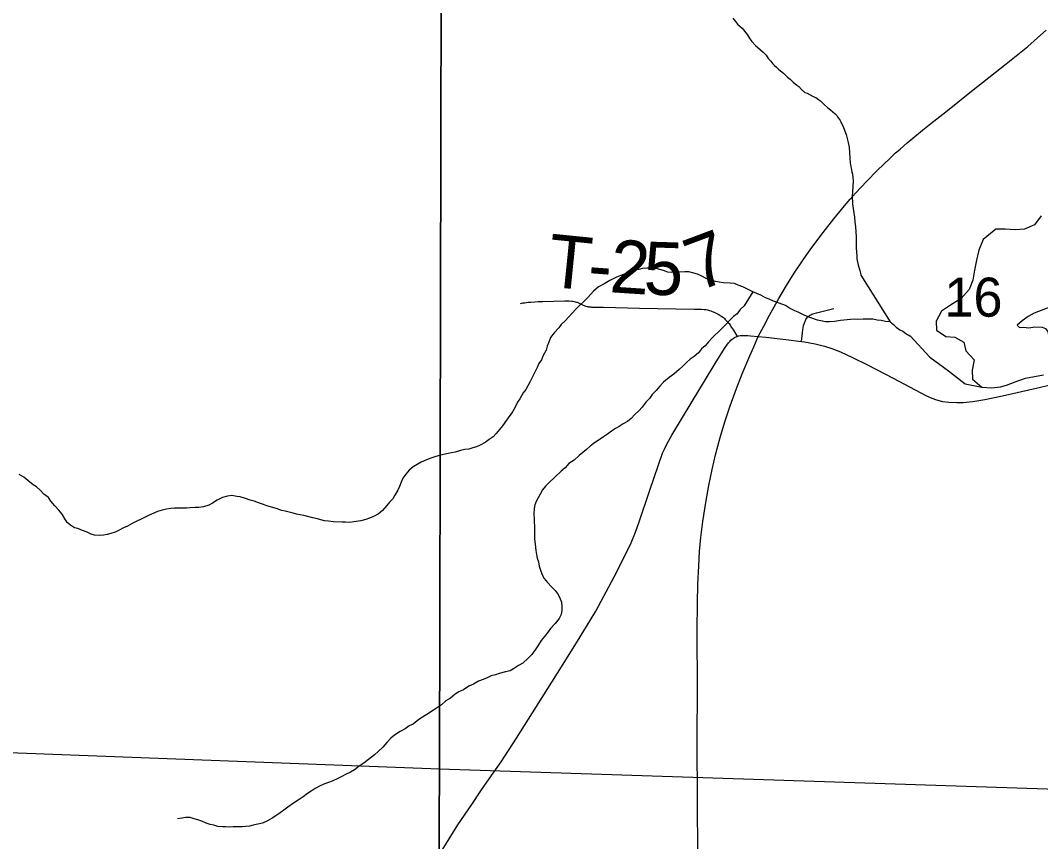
# Model space of a CAD drawing. Extents: x 0 to 34, y 0 to 22.
# Drawn here: x 24.814 to 25.361, y 13.769 to 14.209 of the extents above; entities that cross this region are included whole.
import ezdxf

# ---------------------------------------------------------------- set-up
doc = ezdxf.new("R2010")
doc.units = 0
for name, color, linetype in [('GM_X_County_Road', 7, 'Continuous'), ('GM_X_Major_River', 7, 'Continuous'), ('GM_X_Minor_River', 7, 'Continuous'), ('GM_X_Section', 7, 'Continuous'), ('GM_X_Section_Text', 7, 'Continuous'), ('GM_X_Township_Road', 7, 'Continuous'), ('GM_X_Township_Road_Text', 7, 'Continuous'), ('GM_X_Unincorporated', 7, 'Continuous'), ('GM_X_US_Route', 7, 'Continuous')]:
    doc.layers.add(name, color=color, linetype=linetype)

msp = doc.modelspace()

# ---------------------------------------------------------------- linework, layer by layer
at = {"layer": 'GM_X_County_Road'}
for points in [[(25.03643, 13.7579), (25.04495, 13.77146), (25.04871, 13.77745), (25.05619, 13.78851), (25.06101, 13.79576), (25.06545, 13.80214), (25.07183, 13.81128), (25.08004, 13.82406), (25.08654, 13.83428), (25.10424, 13.86239), (25.11284, 13.87606), (25.1197, 13.88715), (25.1227, 13.8922), (25.13253, 13.91053), (25.13648, 13.91827), (25.14155, 13.92891), (25.14397, 13.9346), (25.14598, 13.94012), (25.15149, 13.95661), (25.15621, 13.97075), (25.15846, 13.9769), (25.15945, 13.97919), (25.16068, 13.98171), (25.1634, 13.98663), (25.17439, 14.00466), (25.18105, 14.01551), (25.18729, 14.02589), (25.19212, 14.0336), (25.19388, 14.03618), (25.19467, 14.03707), (25.19518, 14.03756), (25.19585, 14.03814), (25.19631, 14.0385), (25.19699, 14.03895), (25.19742, 14.03919), (25.1985, 14.03963)], [(25.1985, 14.03963), (25.19941, 14.03989), (25.20017, 14.04005), (25.20098, 14.04014), (25.20169, 14.04018), (25.20254, 14.04018), (25.20329, 14.04015), (25.20417, 14.04011), (25.20572, 14.03998), (25.20974, 14.03956)], [(25.20974, 14.03956), (25.21393, 14.03913), (25.22464, 14.03789), (25.23294, 14.03686)], [(25.23294, 14.03686), (25.23465, 14.03661), (25.2403, 14.03564), (25.24536, 14.03446), (25.24921, 14.03315), (25.25388, 14.03136), (25.26039, 14.02836), (25.2684, 14.02427), (25.27777, 14.01945), (25.28221, 14.01722), (25.29401, 14.01095), (25.30004, 14.00778), (25.30285, 14.00652), (25.30544, 14.00559), (25.3087, 14.00476), (25.31203, 14.00425), (25.31632, 14.00407), (25.3197, 14.00418), (25.32492, 14.00475), (25.33134, 14.00578), (25.34075, 14.00779), (25.35892, 14.01191), (25.3665, 14.01358)]]:
    msp.add_lwpolyline(points, dxfattribs=at)
at = {"layer": 'GM_X_Major_River'}
msp.add_lwpolyline([(25.37171, 14.05751), (25.35771, 14.05216), (25.35463, 14.05034), (25.35134, 14.04796), (25.34862, 14.04556), (25.34992, 14.04439), (25.35201, 14.04452), (25.35486, 14.04426), (25.3581, 14.04475), (25.36208, 14.04465), (25.36396, 14.04384), (25.36524, 14.04191), (25.36557, 14.03963)], dxfattribs=at)
at = {"layer": 'GM_X_Minor_River'}
for points in [[(25.19614, 14.21036), (25.19759, 14.2086), (25.19868, 14.20724), (25.19996, 14.20605), (25.20125, 14.20506), (25.20377, 14.20155), (25.2052, 14.19922), (25.20629, 14.19786), (25.20829, 14.1957), (25.20958, 14.19471), (25.21251, 14.19214), (25.21397, 14.19057), (25.2145, 14.1896), (25.21522, 14.18862), (25.2165, 14.18725), (25.2174, 14.18608), (25.21849, 14.1849), (25.2196, 14.1841), (25.22069, 14.18293), (25.2218, 14.18213), (25.22327, 14.18094), (25.22418, 14.17996), (25.22546, 14.17877), (25.22693, 14.17758), (25.22858, 14.17601), (25.23042, 14.17443), (25.23152, 14.17363), (25.23298, 14.17206), (25.23481, 14.17047), (25.23612, 14.17005), (25.23761, 14.16924), (25.23928, 14.16842), (25.24077, 14.1678), (25.24206, 14.16681), (25.24317, 14.16601), (25.24427, 14.16502), (25.24518, 14.16404), (25.2472, 14.16226), (25.24849, 14.16127), (25.24977, 14.16008), (25.25106, 14.15909), (25.25197, 14.15811), (25.25268, 14.15694), (25.25359, 14.15577), (25.25412, 14.15481), (25.25552, 14.15172), (25.25689, 14.14787), (25.25757, 14.14576), (25.25806, 14.14365), (25.25854, 14.14117), (25.25881, 14.13831), (25.25889, 14.13527), (25.25917, 14.13279), (25.25948, 14.13069), (25.2598, 14.12916), (25.25994, 14.12783), (25.26028, 14.12668)], [(25.26028, 14.12668), (25.26059, 14.12496), (25.26071, 14.12305), (25.2603, 14.11718), (25.26023, 14.1151), (25.26044, 14.11053), (25.26103, 14.10595), (25.26151, 14.10366), (25.2616, 14.10099), (25.26188, 14.09833), (25.26216, 14.09566), (25.26225, 14.093), (25.26233, 14.08995), (25.26241, 14.0871), (25.26252, 14.08482), (25.26264, 14.08292), (25.26276, 14.0812), (25.26339, 14.07776), (25.26423, 14.07489), (25.26456, 14.07355), (25.2649, 14.07239), (25.28064, 14.04735), (25.28229, 14.04597), (25.28376, 14.04459), (25.28579, 14.04319), (25.28727, 14.04238), (25.28893, 14.04118), (25.29116, 14.03996), (25.29126, 14.03991)], [(25.36149, 14.10427), (25.35795, 14.09943), (25.35257, 14.09709), (25.34763, 14.09684), (25.34232, 14.09716), (25.33719, 14.0971), (25.3304, 14.09158), (25.32817, 14.08594), (25.32689, 14.08047), (25.32581, 14.07518), (25.32491, 14.0697), (25.32289, 14.06481), (25.31859, 14.05998), (25.31299, 14.05633), (25.30816, 14.05322), (25.30518, 14.04779), (25.30544, 14.04304), (25.31048, 14.0395), (25.31522, 14.03919), (25.32009, 14.0366), (25.32112, 14.03182), (25.32555, 14.02697), (25.32446, 14.02149), (25.32472, 14.01674), (25.32975, 14.01243), (25.33486, 14.01193), (25.33982, 14.01256), (25.34288, 14.01343)], [(25.28064, 14.04735), (25.27803, 14.04763), (25.27577, 14.04809), (25.2735, 14.04836), (25.27123, 14.04882), (25.26876, 14.04891), (25.2661, 14.04881), (25.26325, 14.04873), (25.26116, 14.0488), (25.25925, 14.04868), (25.25391, 14.04811), (25.25066, 14.04766), (25.2478, 14.04738), (25.2459, 14.04745), (25.24345, 14.04791), (25.24157, 14.04836), (25.238, 14.04963), (25.23481, 14.05089), (25.23126, 14.05254), (25.22939, 14.05336), (25.22659, 14.05479), (25.22436, 14.05621), (25.22099, 14.05747), (25.21798, 14.05853), (25.21574, 14.05956), (25.21368, 14.06039), (25.21126, 14.06181), (25.20695, 14.06349), (25.2047, 14.06452), (25.20153, 14.06615), (25.1991, 14.06719), (25.19704, 14.06803), (25.19476, 14.06811), (25.19116, 14.06843), (25.18889, 14.0687), (25.18681, 14.06915), (25.18418, 14.06982), (25.18193, 14.07066), (25.1795, 14.07189), (25.17726, 14.07292), (25.17519, 14.07356), (25.17255, 14.07423), (25.17046, 14.0743), (25.16627, 14.07407), (25.16323, 14.07399), (25.16133, 14.07406), (25.15889, 14.07491), (25.15513, 14.07599), (25.15267, 14.07627), (25.15, 14.07618), (25.14772, 14.07607), (25.1458, 14.07557), (25.1435, 14.07508), (25.14061, 14.07404), (25.13753, 14.07282), (25.13368, 14.07144), (25.13019, 14.06966), (25.12747, 14.06805), (25.12418, 14.06626), (25.12143, 14.06389), (25.11846, 14.06057), (25.11629, 14.05837), (25.11393, 14.05617), (25.11215, 14.05433), (25.10998, 14.05212), (25.108, 14.04991), (25.10622, 14.04788), (25.10406, 14.04606), (25.10285, 14.0442), (25.10028, 14.04144), (25.0983, 14.03904), (25.09745, 14.0366), (25.09661, 14.03435), (25.09596, 14.03228), (25.09452, 14.02928), (25.09349, 14.02704), (25.09209, 14.025), (25.09125, 14.02294), (25.09024, 14.02107), (25.08901, 14.01864), (25.08736, 14.01509), (25.08513, 14.01117), (25.08373, 14.00932), (25.08191, 14.00615), (25.0807, 14.00429), (25.07946, 14.00167), (25.07804, 13.99906), (25.07484, 13.99461), (25.07264, 13.99165), (25.07105, 13.98961), (25.06926, 13.98758), (25.06768, 13.98574), (25.06553, 13.98429), (25.06338, 13.98266), (25.06067, 13.98123), (25.05874, 13.98035), (25.05663, 13.97986), (25.05451, 13.97917), (25.05241, 13.97887)], [(25.20695, 14.06349), (25.20231, 14.05604), (25.20014, 14.05403), (25.19854, 14.05181), (25.19659, 14.05035), (25.19462, 14.04833), (25.19303, 14.04649), (25.18988, 14.04356), (25.18515, 14.03878), (25.18318, 14.03676), (25.18138, 14.03454), (25.17942, 14.0329), (25.17783, 14.03086), (25.17548, 14.02886), (25.17334, 14.02741), (25.17137, 14.02558), (25.1694, 14.02356), (25.16744, 14.02192), (25.16449, 14.01936), (25.16196, 14.01755), (25.15901, 14.01499), (25.15704, 14.01297), (25.15505, 14.01057), (25.15288, 14.00836), (25.15148, 14.00632), (25.14951, 14.0043), (25.14751, 14.00171), (25.14573, 13.99968), (25.14356, 13.99767), (25.14159, 13.99564), (25.13963, 13.994), (25.13731, 13.99275), (25.13516, 13.99131), (25.13322, 13.99024), (25.13108, 13.98879), (25.12893, 13.98716), (25.12679, 13.98571), (25.12387, 13.98373), (25.12192, 13.98246), (25.11957, 13.98065), (25.11761, 13.979), (25.11565, 13.97736), (25.11369, 13.97572), (25.11113, 13.97315), (25.10821, 13.97135), (25.10623, 13.96914), (25.10408, 13.96732), (25.09739, 13.96109), (25.09561, 13.95925), (25.09402, 13.95722), (25.0928, 13.95498), (25.09177, 13.95292), (25.09076, 13.95106), (25.08993, 13.94918), (25.08967, 13.94729), (25.08938, 13.94445), (25.08966, 13.94159), (25.08984, 13.93625), (25.08974, 13.9334), (25.08984, 13.93074), (25.09012, 13.92806), (25.09057, 13.92481), (25.09087, 13.92252), (25.09118, 13.92061), (25.09187, 13.91868), (25.09236, 13.91638), (25.09304, 13.91426), (25.0939, 13.91176), (25.09497, 13.90963), (25.09679, 13.90747), (25.09881, 13.9055), (25.10082, 13.90333), (25.10246, 13.90118), (25.10351, 13.89886), (25.1042, 13.89694), (25.1045, 13.89464), (25.10443, 13.89274), (25.10416, 13.89047), (25.10294, 13.88823), (25.10095, 13.88564), (25.09838, 13.88288), (25.09717, 13.88102), (25.09518, 13.87862), (25.09339, 13.8764), (25.09198, 13.87417), (25.09017, 13.87138), (25.08837, 13.86897), (25.0864, 13.86695), (25.08345, 13.8642), (25.08112, 13.86296), (25.07859, 13.86115), (25.07665, 13.86007), (25.07416, 13.85959), (25.0709, 13.85876), (25.06878, 13.85807), (25.06648, 13.8574), (25.06435, 13.85633), (25.06223, 13.85545)], [(25.29126, 14.03991), (25.3018, 14.02847), (25.31185, 14.02107), (25.32083, 14.0142), (25.32975, 14.01243)], [(25.34288, 14.01343), (25.34767, 14.01521), (25.35323, 14.01716), (25.358, 14.01818), (25.36277, 14.01901)], [(25.05241, 13.97887), (25.05012, 13.97838), (25.04723, 13.97753), (25.04532, 13.97722), (25.0434, 13.97672), (25.04091, 13.97624), (25.03881, 13.97574), (25.03689, 13.97524), (25.03419, 13.9742), (25.03188, 13.97333), (25.02898, 13.9721), (25.02471, 13.96959), (25.02255, 13.96776), (25.02077, 13.96574), (25.01917, 13.96351), (25.01833, 13.96145), (25.0173, 13.95901), (25.01647, 13.95714), (25.01485, 13.95435), (25.01383, 13.95248), (25.01205, 13.95064), (25.01066, 13.94879), (25.00828, 13.94621), (25.00593, 13.9442), (25.00341, 13.94296), (25.00129, 13.94209), (24.99937, 13.9414), (24.99668, 13.94073), (24.99286, 13.94011), (24.99056, 13.93981), (24.98848, 13.93988), (24.98658, 13.93995), (24.98202, 13.94012), (24.97937, 13.9404), (24.9771, 13.94067), (24.97522, 13.94112), (24.97334, 13.94176), (24.97088, 13.94223), (24.96599, 13.94354), (24.96221, 13.94425), (24.96033, 13.9447), (24.956, 13.9458), (24.95411, 13.94625), (24.95186, 13.94709), (24.94998, 13.94754), (24.9481, 13.94818), (24.94621, 13.94863), (24.94434, 13.94945), (24.94171, 13.95031), (24.93946, 13.95115), (24.93721, 13.9518), (24.93477, 13.95265), (24.93195, 13.95351), (24.93005, 13.95377), (24.92741, 13.95425), (24.92512, 13.95395), (24.92243, 13.95309), (24.91952, 13.95168), (24.91699, 13.95005), (24.91506, 13.94898), (24.91217, 13.94813), (24.90969, 13.94784), (24.90779, 13.94772), (24.90493, 13.94763), (24.90303, 13.94751), (24.90093, 13.9474), (24.89866, 13.94748), (24.89675, 13.94736), (24.89466, 13.94724), (24.89236, 13.94694), (24.89006, 13.94645), (24.88756, 13.94559), (24.88563, 13.94471), (24.88274, 13.94348), (24.87945, 13.94189), (24.87616, 13.9403), (24.87403, 13.93923), (24.87151, 13.9378), (24.86938, 13.93693), (24.86706, 13.93568), (24.86493, 13.93461), (24.86262, 13.93393), (24.86051, 13.93325), (24.8586, 13.93294), (24.85631, 13.93283), (24.85384, 13.93292), (24.85197, 13.93355), (24.84991, 13.93458), (24.84728, 13.93544), (24.84485, 13.93647), (24.84296, 13.93692), (24.84092, 13.93833), (24.83907, 13.93972), (24.83764, 13.94206), (24.83638, 13.94419), (24.83456, 13.94635), (24.83255, 13.94871), (24.83037, 13.95126), (24.8291, 13.9532), (24.82651, 13.95501), (24.82487, 13.95697)], [(24.82487, 13.95697), (24.82266, 13.95895), (24.82079, 13.95997), (24.81803, 13.96235), (24.81581, 13.96414), (24.81339, 13.96556)], [(25.06223, 13.85545), (25.05972, 13.85459), (25.057, 13.85298), (25.0545, 13.85193), (25.05176, 13.84993), (25.04926, 13.84888), (25.04731, 13.84762), (25.04476, 13.84543), (25.04224, 13.844), (25.03988, 13.84199), (25.0356, 13.8391), (25.03209, 13.83675), (25.02879, 13.83478), (25.02684, 13.83333), (25.02468, 13.8315), (25.02256, 13.83063), (25.02041, 13.82899), (25.0177, 13.82757), (25.01477, 13.82558), (25.01281, 13.82394), (25.01064, 13.82174), (25.00846, 13.81915), (25.00591, 13.81696), (25.00394, 13.81513), (25.00081, 13.81258), (24.99827, 13.81058), (24.99574, 13.80895), (24.99319, 13.80695), (24.99106, 13.8057), (24.98835, 13.80446), (24.98641, 13.80339), (24.98428, 13.80233), (24.98119, 13.80092), (24.97927, 13.80022), (24.97676, 13.79936), (24.97445, 13.79831), (24.97212, 13.79706), (24.96998, 13.79561), (24.96803, 13.79435), (24.96569, 13.79253), (24.96296, 13.79073), (24.96043, 13.78911), (24.9575, 13.78693), (24.95536, 13.78548), (24.9534, 13.78403), (24.95106, 13.7824), (24.94912, 13.78114), (24.9466, 13.77971), (24.94389, 13.77848), (24.9414, 13.77781), (24.93891, 13.77732), (24.93699, 13.77682), (24.93489, 13.77671), (24.93298, 13.7764), (24.93032, 13.77649), (24.92823, 13.77638), (24.92632, 13.77625), (24.92424, 13.77652), (24.92234, 13.7764), (24.91988, 13.77668), (24.91781, 13.77732), (24.91574, 13.77777), (24.91367, 13.77842), (24.91142, 13.77945), (24.90917, 13.78029), (24.90729, 13.78074), (24.90503, 13.78139), (24.90275, 13.78147), (24.90065, 13.78117), (24.89835, 13.78068)]]:
    msp.add_lwpolyline(points, dxfattribs=at)
at = {"layer": 'GM_X_Section'}
for points in [[(24.53855, 14.33027), (25.03984, 14.31055), (25.03876, 13.80745), (24.53442, 13.82651)], [(25.03984, 14.31055), (25.53615, 14.29588), (25.53313, 13.79109), (25.03876, 13.80745)]]:
    msp.add_lwpolyline(points, close=True, dxfattribs=at)
at = {"layer": 'GM_X_Township_Road'}
for points in [[(25.08232, 14.05731), (25.08361, 14.05754), (25.08454, 14.05769), (25.08537, 14.05781), (25.08641, 14.05793), (25.08786, 14.05806), (25.08995, 14.05818), (25.09171, 14.05827), (25.09409, 14.05838), (25.10612, 14.05868), (25.10744, 14.05868), (25.10837, 14.05865), (25.10973, 14.05856), (25.11043, 14.05847), (25.11103, 14.05837), (25.11165, 14.05823), (25.11229, 14.05805), (25.11271, 14.05791), (25.113, 14.05779), (25.11377, 14.05745), (25.11549, 14.05663), (25.11676, 14.05604), (25.1174, 14.05582), (25.11798, 14.05566), (25.1184, 14.05558), (25.11866, 14.05554), (25.11912, 14.05549), (25.11929, 14.05548), (25.11998, 14.05542), (25.12037, 14.05539), (25.1227, 14.05539), (25.12682, 14.05533), (25.14617, 14.05485), (25.17545, 14.05422)], [(25.17545, 14.05422), (25.17808, 14.05419), (25.17935, 14.05414), (25.18072, 14.05406), (25.18165, 14.05396), (25.18265, 14.05379), (25.18363, 14.05353), (25.18435, 14.05331), (25.18477, 14.05317), (25.18553, 14.05285), (25.18587, 14.0527)], [(25.18587, 14.0527), (25.18621, 14.05255), (25.18729, 14.05203), (25.18826, 14.05151), (25.18925, 14.05093), (25.19027, 14.05028), (25.19108, 14.04967), (25.19172, 14.04913), (25.19212, 14.04876), (25.19265, 14.04822), (25.19303, 14.04782), (25.19344, 14.04735), (25.1939, 14.04678), (25.19415, 14.04645), (25.19479, 14.04558), (25.19554, 14.04447), (25.19653, 14.0429), (25.1985, 14.03963)], [(25.23441, 14.04627), (25.23466, 14.04698), (25.23493, 14.04764), (25.23519, 14.04821), (25.23541, 14.04863), (25.23572, 14.04913), (25.23592, 14.04944), (25.23627, 14.04987), (25.23656, 14.05018), (25.23695, 14.05053), (25.23711, 14.05065), (25.23747, 14.05092), (25.23761, 14.051), (25.23801, 14.05122), (25.23855, 14.05147), (25.23915, 14.0517), (25.23986, 14.05193), (25.24106, 14.05226), (25.25041, 14.05454)], [(25.23294, 14.03686), (25.23348, 14.04149), (25.23352, 14.04191), (25.23365, 14.04291), (25.23389, 14.04436), (25.23416, 14.04545), (25.23441, 14.04627)], [(25.1985, 14.03963), (25.19941, 14.03989), (25.20017, 14.04005), (25.20098, 14.04014), (25.20169, 14.04018), (25.20254, 14.04018), (25.20329, 14.04015), (25.20417, 14.04011), (25.20572, 14.03998), (25.20974, 14.03956)], [(25.20974, 14.03956), (25.21393, 14.03913), (25.22464, 14.03789), (25.23294, 14.03686)]]:
    msp.add_lwpolyline(points, dxfattribs=at)
at = {"layer": 'GM_X_Unincorporated'}
for points in [[(24.53388, 13.43613), (25.0365, 13.43613), (25.03876, 13.80745), (24.53442, 13.82651)], [(25.0365, 13.43613), (25.53368, 13.43613), (25.53313, 13.79109), (25.03876, 13.80745)]]:
    msp.add_lwpolyline(points, close=True, dxfattribs=at)
at = {"layer": 'GM_X_US_Route'}
msp.add_lwpolyline([(25.17737, 13.76331), (25.17713, 13.78879), (25.17706, 13.82389), (25.17717, 13.8503), (25.17708, 13.88168), (25.17718, 13.8966), (25.17743, 13.90655), (25.17787, 13.91649), (25.17837, 13.92425), (25.17906, 13.93169), (25.18013, 13.94033), (25.18167, 13.95048), (25.18329, 13.95968), (25.18502, 13.96821), (25.18687, 13.97609), (25.18939, 13.9854), (25.19191, 13.99374), (25.19474, 14.00231), (25.19812, 14.01167), (25.20119, 14.01949), (25.20536, 14.02921), (25.20736, 14.03397), (25.20921, 14.0383), (25.20974, 14.03956), (25.21271, 14.04503), (25.21586, 14.05094), (25.22083, 14.05992), (25.22495, 14.06689), (25.2291, 14.07347), (25.23392, 14.08073), (25.23804, 14.08659), (25.24455, 14.09531), (25.25028, 14.10268), (25.25604, 14.10963), (25.25916, 14.11329), (25.262, 14.11641), (25.26791, 14.12281), (25.27379, 14.12881), (25.2803, 14.13506), (25.2835, 14.13806), (25.28585, 14.14007), (25.28964, 14.1434), (25.29271, 14.14592), (25.29794, 14.15028), (25.30237, 14.15377), (25.31039, 14.16016), (25.32424, 14.17121), (25.34277, 14.18585), (25.35439, 14.19518), (25.3595, 14.19979), (25.36425, 14.2039)], dxfattribs=at)

# ---------------------------------------------------------------- texts
at = {"layer": 'GM_X_Section_Text'}
msp.add_text('16', height=0.020928, rotation=0, dxfattribs=at).set_placement((25.30967, 14.0502))
at = {"layer": 'GM_X_Township_Road_Text'}
for s, rotation, p in [('7', 20.5192, (25.17724, 14.06356)), ('T', 354.1954, (25.09594, 14.0665)), ('2', 356.2031, (25.12965, 14.06337)), ('5', 358.1592, (25.14803, 14.06217)), ('-', 355.5499, (25.11777, 14.06429))]:
    msp.add_text(s, height=0.02841, rotation=rotation, dxfattribs=at).set_placement(p)

doc.saveas('drawing.dxf')
